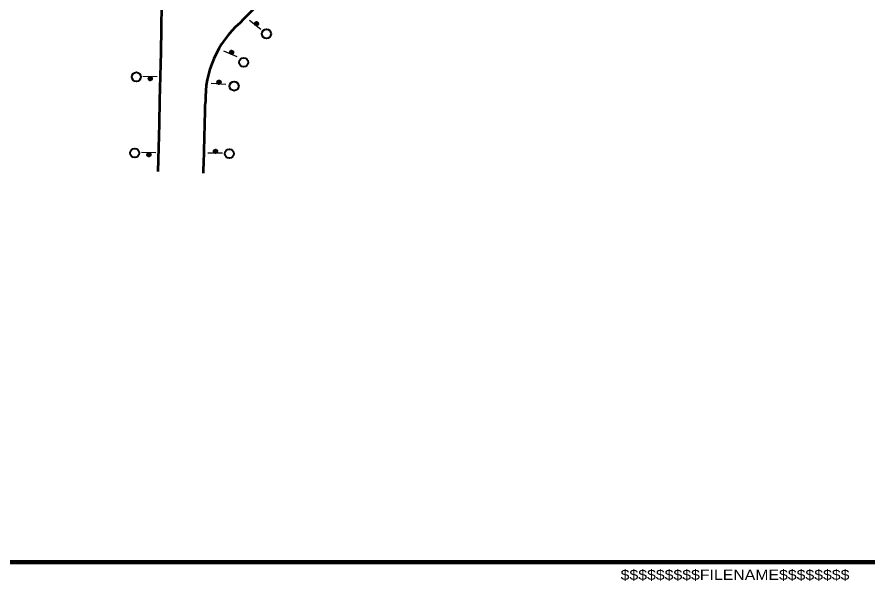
# Model space of a CAD drawing. Extents: x 393 to 1249, y -102 to 530.
# Drawn here: x 840.2 to 1022, y -6.9 to 113.6 of the extents above; entities that cross this region are included whole.
import ezdxf

# ---------------------------------------------------------------- set-up
doc = ezdxf.new("R2010")
doc.units = 0
doc.header["$LTSCALE"] = 0.97
doc.layers.add('1', color=7, linetype='Continuous', lineweight=40)
doc.layers.add('4', color=7, linetype='Continuous', lineweight=25)

msp = doc.modelspace()

# ---------------------------------------------------------------- linework, layer by layer
at = {"layer": '1', "lineweight": 158}
msp.add_line((1242.1684, -2.8845), (450.5684, -2.8845), dxfattribs=at)
at = {"layer": '1'}
for centre, radius in [((891.344, 112.1984), 0.3791), ((891.3455, 112.1847), 0.35), ((891.3412, 112.2257), 0.3402), ((891.3516, 112.1923), 0.3305), ((891.344, 112.1984), 0.3013), ((891.344, 112.1984), 0.2819), ((891.3516, 112.1923), 0.2722), ((891.3516, 112.1923), 0.2527), ((891.3577, 112.1998), 0.2335), ((891.3638, 112.2074), 0.2138), ((891.3638, 112.2074), 0.1944), ((891.376, 112.2225), 0.175), ((891.3667, 112.18), 0.1555), ((891.4034, 112.2254), 0.1555), ((891.3591, 112.1861), 0.1069), ((891.2627, 112.3142), 0.00972), ((891.402, 112.239), 0.1461), ((891.4156, 112.2405), 0.1166), ((891.4217, 112.248), 0.0977), ((891.4279, 112.2556), 0.0778), ((891.4401, 112.2707), 0.0583), ((891.4523, 112.2858), 0.0389), ((891.4646, 112.3009), 0.0194), ((893.4702, 110.0355), 0.972), ((886.0288, 106.0728), 0.3791), ((886.019, 106.0985), 0.3402), ((886.0338, 106.06), 0.35), ((886.0377, 106.0689), 0.3305), ((886.0288, 106.0728), 0.3013), ((886.0288, 106.0728), 0.2819), ((886.0377, 106.0689), 0.2722), ((886.0377, 106.0689), 0.2527), ((886.0417, 106.0778), 0.2335), ((886.0456, 106.0866), 0.2138), ((886.0456, 106.0866), 0.1944), ((886.0535, 106.1044), 0.175), ((886.0555, 106.061), 0.1555), ((885.9203, 106.1637), 0.00972), ((886.0792, 106.1143), 0.1555), ((886.0743, 106.1271), 0.1461), ((886.0466, 106.0649), 0.1069), ((886.0871, 106.132), 0.1166), ((886.0911, 106.1409), 0.0977), ((886.095, 106.1498), 0.0778), ((886.1029, 106.1675), 0.0583), ((886.1108, 106.1853), 0.0389), ((886.1187, 106.2031), 0.0194), ((888.5908, 103.9362), 0.972), ((865.6678, 100.8358), 0.972), ((868.6461, 100.4671), 0.3791), ((868.6263, 100.448), 0.3402), ((868.656, 100.4767), 0.35), ((868.6558, 100.4669), 0.3305), ((868.6461, 100.4671), 0.3013), ((868.6461, 100.4671), 0.2819), ((868.6558, 100.4669), 0.2722), ((868.6558, 100.4669), 0.2527), ((868.6556, 100.4572), 0.2335), ((868.6555, 100.4475), 0.2138), ((868.6555, 100.4475), 0.1944), ((868.6551, 100.4281), 0.175), ((868.5094, 100.4306), 0.00972), ((868.6643, 100.3987), 0.1461), ((868.6742, 100.4083), 0.1555), ((868.6752, 100.4666), 0.1555), ((868.6739, 100.3889), 0.1166), ((868.6655, 100.4668), 0.1069), ((868.6737, 100.3791), 0.0977), ((868.6736, 100.3694), 0.0778), ((868.6732, 100.35), 0.0583), ((868.6729, 100.3305), 0.0389), ((868.6725, 100.3111), 0.0194), ((883.3141, 99.6875), 0.3791), ((883.2961, 99.7082), 0.3402), ((883.3231, 99.6771), 0.35), ((883.3238, 99.6868), 0.3305), ((883.3141, 99.6875), 0.3013), ((883.3141, 99.6875), 0.2819), ((883.3238, 99.6868), 0.2722), ((883.3238, 99.6868), 0.2527), ((883.3245, 99.6965), 0.2335), ((883.3252, 99.7062), 0.2138), ((883.3252, 99.7062), 0.1944), ((883.3265, 99.7256), 0.175), ((883.1811, 99.7357), 0.00972), ((883.3432, 99.6854), 0.1555), ((883.3473, 99.7436), 0.1555), ((883.3383, 99.754), 0.1461), ((883.3335, 99.6861), 0.1069), ((883.3486, 99.763), 0.1166), ((883.3493, 99.7727), 0.0977), ((883.35, 99.7824), 0.0778), ((883.3513, 99.8018), 0.0583), ((883.3527, 99.8212), 0.0389), ((883.3541, 99.8406), 0.0194), ((886.5577, 98.8536), 0.972), ((865.312, 84.5711), 0.972), ((868.3411, 84.2026), 0.3791), ((868.3214, 84.1835), 0.3402), ((868.351, 84.2121), 0.35), ((868.3508, 84.2024), 0.3305), ((868.3411, 84.2026), 0.3013), ((868.3411, 84.2026), 0.2819), ((868.3508, 84.2024), 0.2722), ((868.3508, 84.2024), 0.2527), ((868.3507, 84.1927), 0.2335), ((868.3505, 84.183), 0.2138), ((868.3505, 84.183), 0.1944), ((868.3502, 84.1635), 0.175), ((868.2044, 84.1661), 0.00972), ((868.3594, 84.1342), 0.1461), ((868.3693, 84.1437), 0.1555), ((868.3703, 84.2021), 0.1555), ((868.3689, 84.1243), 0.1166), ((868.3606, 84.2022), 0.1069), ((868.3688, 84.1146), 0.0977), ((868.3686, 84.1049), 0.0778), ((868.3682, 84.0854), 0.0583), ((868.3679, 84.066), 0.0389), ((868.3676, 84.0466), 0.0194), ((882.5727, 84.9336), 0.3791), ((882.5529, 84.9527), 0.3402), ((882.5826, 84.924), 0.35), ((882.5824, 84.9338), 0.3305), ((882.5727, 84.9336), 0.3013), ((882.5727, 84.9336), 0.2819), ((882.5824, 84.9338), 0.2722), ((882.5824, 84.9338), 0.2527), ((882.5822, 84.9435), 0.2335), ((882.582, 84.9532), 0.2138), ((882.582, 84.9532), 0.1944), ((882.5817, 84.9726), 0.175), ((882.4359, 84.9701), 0.00972), ((882.5909, 85.002), 0.1461), ((882.6008, 84.9924), 0.1555), ((882.6018, 84.9341), 0.1555), ((882.6005, 85.0118), 0.1166), ((882.5921, 84.9339), 0.1069), ((882.6003, 85.0216), 0.0977), ((882.6001, 85.0313), 0.0778), ((882.5998, 85.0507), 0.0583), ((882.5994, 85.0702), 0.0389), ((882.5991, 85.0896), 0.0194), ((885.5412, 84.4187), 0.972)]:
    msp.add_circle(centre, radius, dxfattribs=at)
at = {"layer": '1', "lineweight": 53}
for centre, radius, start, end in [((-1822.5792, 162.2285), 2694.1082, 358.26332, 1.73668), ((963.3338, 40.1068), 104.5427, 113.77313, 136.30699), ((902.0414, 96.0982), 21.6265, 131.38429, 181.69919), ((-1822.5792, 162.2285), 2703.8282, 358.26332, 358.58492)]:
    msp.add_arc(centre, radius, start, end, dxfattribs=at)
at = {"layer": '4'}
for p, q in [((892.2429, 110.9452), (889.8256, 112.9028)), ((887.2215, 105.095), (884.3797, 106.3602)), ((870.1402, 100.8494), (867.0299, 100.9035)), ((884.7692, 99.1764), (881.6661, 99.3935)), ((869.8352, 84.5848), (866.725, 84.639)), ((884.0667, 84.5513), (880.9565, 84.4971))]:
    msp.add_line(p, q, dxfattribs=at)
for centre in [(891.3365, 112.2045), (886.02, 106.0768), (868.6364, 100.4673), (883.3044, 99.6881), (868.3314, 84.2027), (882.5629, 84.9334)]:
    msp.add_circle(centre, 0.3985, dxfattribs=at)

# ---------------------------------------------------------------- texts
at = {"layer": '1', "width": 1.15}
msp.add_text('$$$$$$$$$FILENAME$$$$$$$$', height=2.2, dxfattribs=at).set_placement((969.1684, -6.6845))

doc.saveas('drawing.dxf')
